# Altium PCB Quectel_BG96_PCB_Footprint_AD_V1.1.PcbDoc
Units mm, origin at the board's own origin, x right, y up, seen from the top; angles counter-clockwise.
Board outline 152.4 x 101.6 mm, 4 copper layers (Top, Inner Layer 2, Inner Layer 3, Bottom), stack 0.899 mm thick; 1 components, 0 nets, 102 pads, 0 vias.
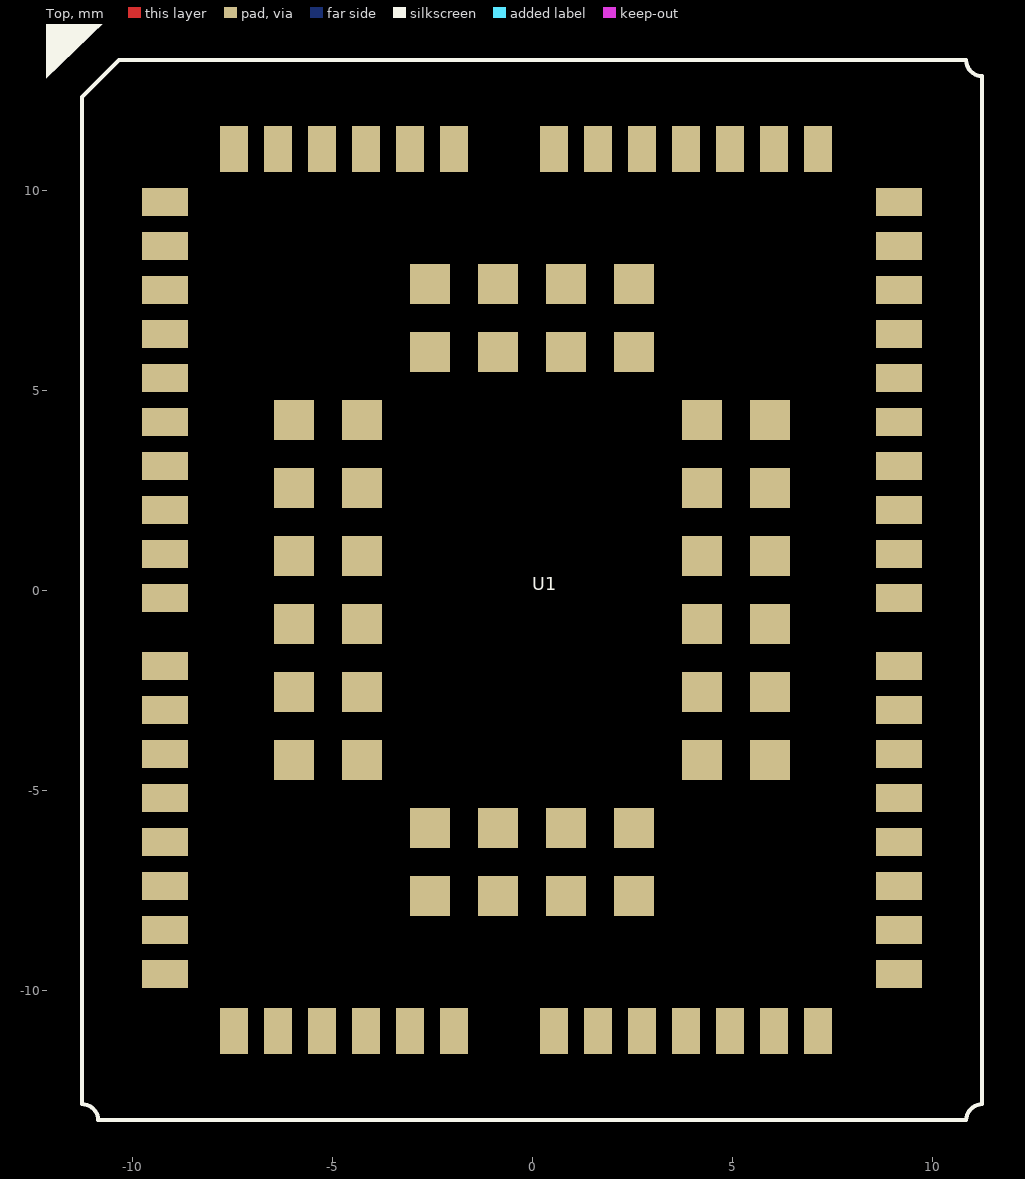
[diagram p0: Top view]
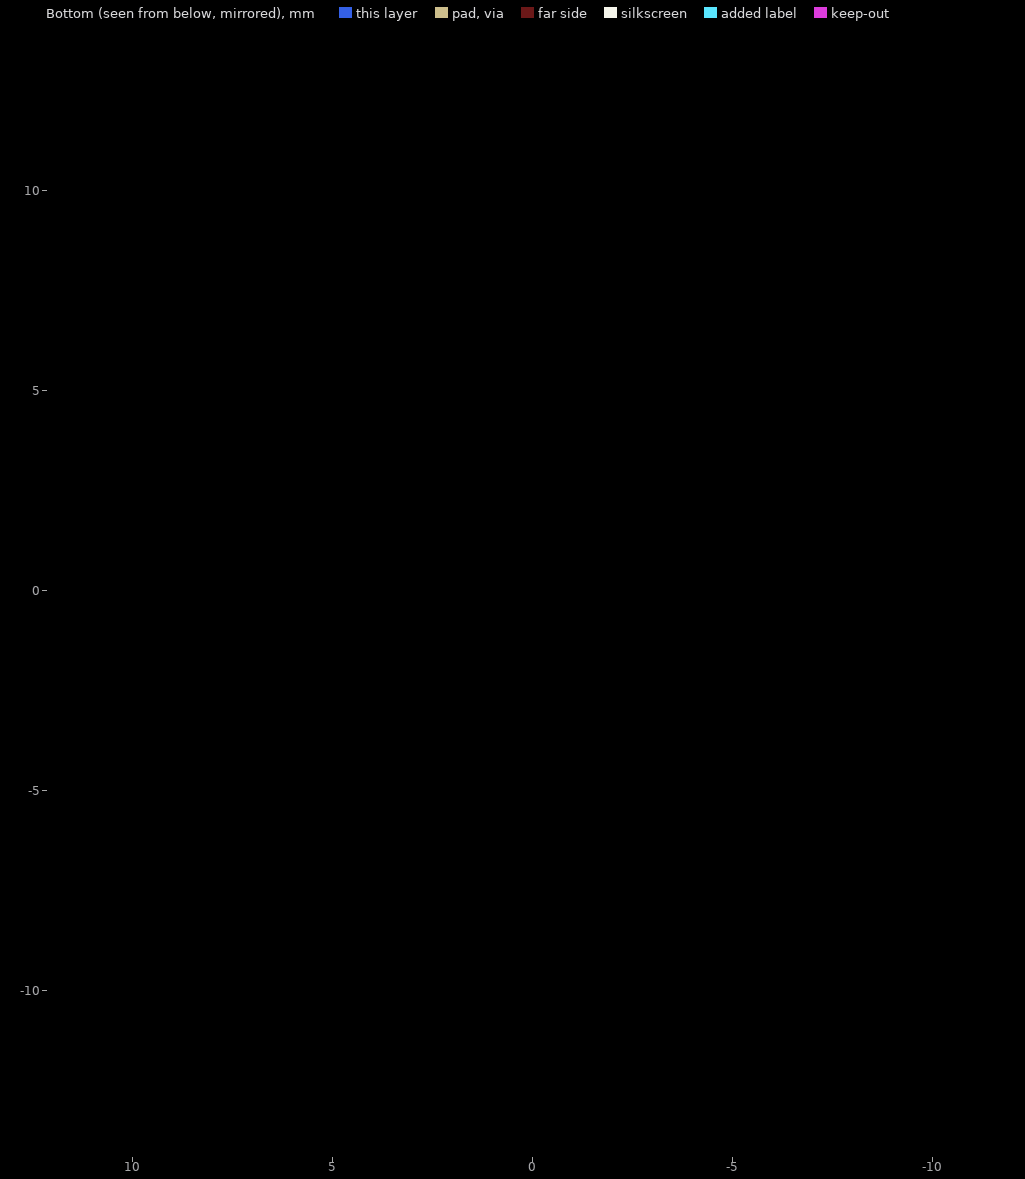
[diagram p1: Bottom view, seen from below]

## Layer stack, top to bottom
Top: signal copper 0.0343
Dielectric: dielectric 0.254, FR-4, Dk 4.3
Inner Layer 2: signal copper 0.0343
Dielectric: dielectric 0.254, FR-4, Dk 4.3
Inner Layer 3: signal copper 0.0343
Dielectric: dielectric 0.254, FR-4, Dk 4.3
Bottom: signal copper 0.0343

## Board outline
-228.6,-228.6 -76.2,-228.6 -76.2,-127 -228.6,-127

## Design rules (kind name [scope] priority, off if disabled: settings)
Clearance "'Default' PADS rule_18" [All] p1: gap=0.152
Clearance "'Default' PADS rule_15" [IsVia vs IsVia] p2: gap=0.152
ComponentClearance "'Default' PADS rule_12" [All] p1: gap=0.152 collisioncheckmode=3 verticalgap=0.254 showdistances=FALSE
FlightTimeFalling "'Default' PADS rule_10" [All] p1: maximum=10.00
FlightTimeRising "'Default' PADS rule_9" [All] p1: maximum=10.00
Length "'Default' PADS rule_5" [All] p1: maxlimit=1270 minlimit=0
MatchedLengths "'Default' PADS rule_11" [InNetClass('All Nets')] p1: tolerance=5.08 checknetsindiffpair=TRUE checkdiffpairvsdiffpair=TRUE checkothers=TRUE
MaxMinImpedance "'Default' PADS rule_8" [All] p1: minimum=50.00 maximum=150.0
ParallelSegment "'Default' PADS rule_7" [All] p1: limit=25.4 gap=5.08
ParallelSegment "'Default' PADS rule_6" [All] p2: limit=25.4 gap=5.08
PlaneClearance "'Default' PADS rule_14" [All] p1: clearance=0.152
PlaneConnect "Power Plane Connect Style - Via from round thru-hole global defaults" [IsVia] p1: planeconnectstyle=Relief reliefexpansion=0.508 reliefentries=4 reliefconductorwidth=0.381 reliefairgap=0.254
PlaneConnect "Power Plane Connect Style - Round thru-hole pad from global defaults" [IsPad And OnMultiLayer And (PadShape_MidLayer1 = 'Round') And (PadXSize_MidLayer1 = PadYSize_MidLayer1)] p2: planeconnectstyle=Relief reliefexpansion=0.508 reliefentries=4 reliefconductorwidth=0.381 reliefairgap=0.254
PlaneConnect "Power Plane Connect Style - Square thru-hole pad from global defaults" [IsPad And OnMultiLayer And ((PadShape_MidLayer1 = 'Rectangular') Or (PadShape_MidLayer1 = 'Octagonal') Or (PadShape_MidLayer1 = 'Rounded Rectangle')) And (PadXSize_MidLayer1 = PadYSize_MidLayer1)] p3: planeconnectstyle=Relief reliefexpansion=0.508 reliefentries=4 reliefconductorwidth=0.381 reliefairgap=0.254
PlaneConnect "Power Plane Connect Style - Rect thru-hole pad from global defaults" [IsPad And OnMultiLayer And ((PadShape_MidLayer1 = 'Rectangular') Or (PadShape_MidLayer1 = 'Octagonal') Or (PadShape_MidLayer1 = 'Rounded Rectangle')) And (PadXSize_MidLayer1 <> PadYSize_MidLayer1)] p4: planeconnectstyle=Relief reliefexpansion=0.508 reliefentries=4 reliefconductorwidth=0.381 reliefairgap=0.254
PlaneConnect "Power Plane Connect Style - Square-rect thru-hole pad from global defaults" [IsPad And OnMultiLayer And (PadShape_MidLayer1 = 'Rounded Rectangle') And (PadXSize_MidLayer1 = PadYSize_MidLayer1) And (Pad_CornerRadius_MidLayer1 = '0%')] p5: planeconnectstyle=Relief reliefexpansion=0.508 reliefentries=4 reliefconductorwidth=0.381 reliefairgap=0.254
PlaneConnect "Power Plane Connect Style - Oval thru-hole pad from global defaults" [IsPad And OnMultiLayer And (PadShape_MidLayer1 = 'Round') And (PadXSize_MidLayer1 <> PadYSize_MidLayer1)] p6: planeconnectstyle=Relief reliefexpansion=0.508 reliefentries=4 reliefconductorwidth=0.381 reliefairgap=0.254
PlaneConnect "Power Plane Connect Style - Round-oval thru-hole pad from global defaults" [IsPad And OnMultiLayer And (PadShape_MidLayer1 = 'Rounded Rectangle') And (PadXSize_MidLayer1 = PadYSize_MidLayer1) And (Pad_CornerRadius_MidLayer1 = '100%')] p7: planeconnectstyle=Relief reliefexpansion=0.508 reliefentries=4 reliefconductorwidth=0.381 reliefairgap=0.254
PolygonConnect "Polygon Connect Style - Bottom Round SMD from global defaults" [IsSMTPin And (PadShape_BottomLayer = 'Round') And (PadXSize_BottomLayer = PADYSize_BottomLayer) vs Layer = 'Bottom'] p1: connectstyle=Relief reliefconductorwidth=0.254 reliefentries=4 polygonreliefangle="45 Angle" airgapwidth=0.254
PolygonConnect "Polygon Connect Style - Top Round SMD from global defaults" [IsSMTPin And (PadShape_TopLayer = 'Round') And (PadXSize_TopLayer = PADYSize_TopLayer) vs Layer = 'Top'] p2: connectstyle=Relief reliefconductorwidth=0.254 reliefentries=4 polygonreliefangle="45 Angle" airgapwidth=0.254
PolygonConnect "Polygon Connect Style - Bottom Square SMD from global defaults 1" [IsSMTPin And (PadShape_BottomLayer = 'Rectangular') And (PadXSize_BottomLayer = PADYSize_BottomLayer) vs Layer = 'Bottom'] p3: connectstyle=Relief reliefconductorwidth=0.254 reliefentries=4 polygonreliefangle="45 Angle" airgapwidth=0.254
PolygonConnect "Polygon Connect Style - Bottom Square SMD from global defaults 2" [IsSMTPin And (PadShape_BottomLayer = 'Octagonal') And (PadXSize_BottomLayer = PADYSize_BottomLayer) vs Layer = 'Bottom'] p4: connectstyle=Relief reliefconductorwidth=0.254 reliefentries=4 polygonreliefangle="45 Angle" airgapwidth=0.254
PolygonConnect "Polygon Connect Style - Bottom Square SMD from global defaults 3" [IsSMTPin And (PadShape_BottomLayer = 'Rounded Rectangle') And (PadXSize_BottomLayer = PADYSize_BottomLayer) vs Layer = 'Bottom'] p5: connectstyle=Relief reliefconductorwidth=0.254 reliefentries=4 polygonreliefangle="45 Angle" airgapwidth=0.254
PolygonConnect "Polygon Connect Style - Top Square SMD from global defaults 1" [IsSMTPin And (PadShape_TopLayer = 'Rectangular') And (PadXSize_TopLayer = PADYSize_TopLayer) vs Layer = 'Top'] p6: connectstyle=Relief reliefconductorwidth=0.254 reliefentries=4 polygonreliefangle="45 Angle" airgapwidth=0.254
PolygonConnect "Polygon Connect Style - Top Square SMD from global defaults 2" [IsSMTPin And (PadShape_TopLayer = 'Octagonal') And (PadXSize_TopLayer = PADYSize_TopLayer) vs Layer = 'Top'] p7: connectstyle=Relief reliefconductorwidth=0.254 reliefentries=4 polygonreliefangle="45 Angle" airgapwidth=0.254
PolygonConnect "Polygon Connect Style - Top Square SMD from global defaults 3" [IsSMTPin And (PadShape_TopLayer = 'Rounded Rectangle') And (PadXSize_TopLayer = PADYSize_TopLayer) vs Layer = 'Top'] p8: connectstyle=Relief reliefconductorwidth=0.254 reliefentries=4 polygonreliefangle="45 Angle" airgapwidth=0.254
PolygonConnect "Polygon Connect Style - Bottom Rect SMD from global defaults 1" [IsSMTPin And (PadShape_BottomLayer = 'Rectangular') And (PadXSize_BottomLayer <> PADYSize_BottomLayer) vs Layer = 'Bottom'] p9: connectstyle=Relief reliefconductorwidth=0.254 reliefentries=4 polygonreliefangle="45 Angle" airgapwidth=0.254
PolygonConnect "Polygon Connect Style - Bottom Rect SMD from global defaults 2" [IsSMTPin And (PadShape_BottomLayer = 'Octagonal') And (PadXSize_BottomLayer <> PADYSize_BottomLayer) vs Layer = 'Bottom'] p10: connectstyle=Relief reliefconductorwidth=0.254 reliefentries=4 polygonreliefangle="45 Angle" airgapwidth=0.254
PolygonConnect "Polygon Connect Style - Bottom Rect SMD from global defaults 3" [IsSMTPin And (PadShape_BottomLayer = 'Rounded Rectangle') And (PadXSize_BottomLayer <> PADYSize_BottomLayer) vs Layer = 'Bottom'] p11: connectstyle=Relief reliefconductorwidth=0.254 reliefentries=4 polygonreliefangle="45 Angle" airgapwidth=0.254
PolygonConnect "Polygon Connect Style - Bottom Square-rect SMD pad from global defaults" [IsSMTPin And (PadShape_BottomLayer = 'Rounded Rectangle') And (PadXSize_BottomLayer = PADYSize_BottomLayer) And (Pad_CornerRadius_BottomLayer = '0%') vs Layer = 'Bottom'] p12: connectstyle=Relief reliefconductorwidth=0.254 reliefentries=4 polygonreliefangle="45 Angle" airgapwidth=0.254
PolygonConnect "Polygon Connect Style - Top Rect SMD from global defaults 1" [IsSMTPin And (PadShape_TopLayer = 'Rectangular') And (PadXSize_TopLayer <> PADYSize_TopLayer) vs Layer = 'Top'] p13: connectstyle=Relief reliefconductorwidth=0.254 reliefentries=4 polygonreliefangle="45 Angle" airgapwidth=0.254
PolygonConnect "Polygon Connect Style - Top Rect SMD from global defaults 2" [IsSMTPin And (PadShape_TopLayer = 'Octagonal') And (PadXSize_TopLayer <> PADYSize_TopLayer) vs Layer = 'Top'] p14: connectstyle=Relief reliefconductorwidth=0.254 reliefentries=4 polygonreliefangle="45 Angle" airgapwidth=0.254
PolygonConnect "Polygon Connect Style - Top Rect SMD from global defaults 3" [IsSMTPin And (PadShape_TopLayer = 'Rounded Rectangle') And (PadXSize_TopLayer <> PADYSize_TopLayer) vs Layer = 'Top'] p15: connectstyle=Relief reliefconductorwidth=0.254 reliefentries=4 polygonreliefangle="45 Angle" airgapwidth=0.254
PolygonConnect "Polygon Connect Style - Top Square-rect SMD pad from global defaults" [IsSMTPin And (PadShape_TopLayer = 'Rounded Rectangle') And (PadXSize_TopLayer = PADYSize_TopLayer) And (Pad_CornerRadius_TopLayer = '0%') vs Layer = 'Top'] p16: connectstyle=Relief reliefconductorwidth=0.254 reliefentries=4 polygonreliefangle="45 Angle" airgapwidth=0.254
PolygonConnect "Polygon Connect Style - Bottom Oval SMD from global defaults" [IsSMTPin And (PadShape_BottomLayer = 'Round') And (PadXSize_BottomLayer <> PADYSize_BottomLayer) vs Layer = 'Bottom'] p17: connectstyle=Relief reliefconductorwidth=0.254 reliefentries=4 polygonreliefangle="45 Angle" airgapwidth=0.254
PolygonConnect "Polygon Connect Style - Bottom Round-oval SMD pad from global defaults" [IsSMTPin And (PadShape_BottomLayer = 'Rounded Rectangle') And (PadXSize_BottomLayer = PADYSize_BottomLayer) And (Pad_CornerRadius_BottomLayer = '100%') vs Layer = 'Bottom'] p18: connectstyle=Relief reliefconductorwidth=0.254 reliefentries=4 polygonreliefangle="45 Angle" airgapwidth=0.254
PolygonConnect "Polygon Connect Style - Top Oval SMD from global defaults" [IsSMTPin And (PadShape_TopLayer = 'Round') And (PadXSize_TopLayer <> PADYSize_TopLayer) vs Layer = 'Top'] p19: connectstyle=Relief reliefconductorwidth=0.254 reliefentries=4 polygonreliefangle="45 Angle" airgapwidth=0.254
PolygonConnect "Polygon Connect Style - Top Round-oval SMD pad from global defaults" [IsSMTPin And (PadShape_TopLayer = 'Rounded Rectangle') And (PadXSize_TopLayer = PADYSize_TopLayer) And (Pad_CornerRadius_TopLayer = '100%') vs Layer = 'Top'] p20: connectstyle=Relief reliefconductorwidth=0.254 reliefentries=4 polygonreliefangle="45 Angle" airgapwidth=0.254
PolygonConnect "Polygon Connect Style - Via from round thru-hole global defaults_21" [IsVia] p21: connectstyle=Relief reliefconductorwidth=0.381 reliefentries=4 polygonreliefangle="45 Angle" airgapwidth=0.254
PolygonConnect "Polygon Connect Style - Bottom Round thru-hole pad from global defaults" [IsPad And OnMultiLayer And (PadShape_BottomLayer = 'Round') And (PadXSize_BottomLayer = PADYSize_BottomLayer) vs Layer = 'Bottom'] p22: connectstyle=Relief reliefconductorwidth=0.381 reliefentries=4 polygonreliefangle="45 Angle" airgapwidth=0.254
PolygonConnect "Polygon Connect Style - Via from round thru-hole global defaults_20" [IsVia] p23: connectstyle=Relief reliefconductorwidth=0.381 reliefentries=4 polygonreliefangle="45 Angle" airgapwidth=0.254
PolygonConnect "Polygon Connect Style - Inner Layer 3 Round thru-hole pad from global defaults" [IsPad And OnMultiLayer And (PadShape_MidLayer2 = 'Round') And (PadXSize_MidLayer2 = PADYSize_MidLayer2) vs Layer = 'Inner Layer 3'] p24: connectstyle=Relief reliefconductorwidth=0.381 reliefentries=4 polygonreliefangle="45 Angle" airgapwidth=0.254
PolygonConnect "Polygon Connect Style - Via from round thru-hole global defaults_19" [IsVia] p25: connectstyle=Relief reliefconductorwidth=0.381 reliefentries=4 polygonreliefangle="45 Angle" airgapwidth=0.254
PolygonConnect "Polygon Connect Style - Inner Layer 2 Round thru-hole pad from global defaults" [IsPad And OnMultiLayer And (PadShape_MidLayer1 = 'Round') And (PadXSize_MidLayer1 = PADYSize_MidLayer1) vs Layer = 'Inner Layer 2'] p26: connectstyle=Relief reliefconductorwidth=0.381 reliefentries=4 polygonreliefangle="45 Angle" airgapwidth=0.254
PolygonConnect "Polygon Connect Style - Via from round thru-hole global defaults" [IsVia] p27: connectstyle=Relief reliefconductorwidth=0.381 reliefentries=4 polygonreliefangle="45 Angle" airgapwidth=0.254
PolygonConnect "Polygon Connect Style - Top Round thru-hole pad from global defaults" [IsPad And OnMultiLayer And (PadShape_TopLayer = 'Round') And (PadXSize_TopLayer = PADYSize_TopLayer) vs Layer = 'Top'] p28: connectstyle=Relief reliefconductorwidth=0.381 reliefentries=4 polygonreliefangle="45 Angle" airgapwidth=0.254
PolygonConnect "Polygon Connect Style - Bottom Square thru-hole pad from global defaults" [IsPad And OnMultiLayer And ((PadShape_BottomLayer = 'Rectangular') Or (PadShape_BottomLayer = 'Octagonal') Or (PadShape_BottomLayer = 'Rounded Rectangle')) And (PadXSize_BottomLayer = PADYSize_BottomLayer) vs Layer = 'Bottom'] p29: connectstyle=Relief reliefconductorwidth=0.381 reliefentries=4 polygonreliefangle="45 Angle" airgapwidth=0.254
PolygonConnect "Polygon Connect Style - Inner Layer 3 Square thru-hole pad from global defaults" [IsPad And OnMultiLayer And ((PadShape_MidLayer2 = 'Rectangular') Or (PadShape_MidLayer2 = 'Octagonal') Or (PadShape_MidLayer2 = 'Rounded Rectangle')) And (PadXSize_MidLayer2 = PADYSize_MidLayer2) vs Layer = 'Inner Layer 3'] p30: connectstyle=Relief reliefconductorwidth=0.381 reliefentries=4 polygonreliefangle="45 Angle" airgapwidth=0.254
PolygonConnect "Polygon Connect Style - Inner Layer 2 Square thru-hole pad from global defaults" [IsPad And OnMultiLayer And ((PadShape_MidLayer1 = 'Rectangular') Or (PadShape_MidLayer1 = 'Octagonal') Or (PadShape_MidLayer1 = 'Rounded Rectangle')) And (PadXSize_MidLayer1 = PADYSize_MidLayer1) vs Layer = 'Inner Layer 2'] p31: connectstyle=Relief reliefconductorwidth=0.381 reliefentries=4 polygonreliefangle="45 Angle" airgapwidth=0.254
PolygonConnect "Polygon Connect Style - Top Square thru-hole pad from global defaults" [IsPad And OnMultiLayer And ((PadShape_TopLayer = 'Rectangular') Or (PadShape_TopLayer = 'Octagonal') Or (PadShape_TopLayer = 'Rounded Rectangle')) And (PadXSize_TopLayer = PADYSize_TopLayer) vs Layer = 'Top'] p32: connectstyle=Relief reliefconductorwidth=0.381 reliefentries=4 polygonreliefangle="45 Angle" airgapwidth=0.254
PolygonConnect "Polygon Connect Style - Bottom Rect thru-hole pad from global defaults" [IsPad And OnMultiLayer And ((PadShape_BottomLayer = 'Rectangular') Or (PadShape_BottomLayer = 'Octagonal') Or (PadShape_BottomLayer = 'Rounded Rectangle')) And (PadXSize_BottomLayer <> PADYSize_BottomLayer) vs Layer = 'Bottom'] p33: connectstyle=Relief reliefconductorwidth=0.381 reliefentries=4 polygonreliefangle="45 Angle" airgapwidth=0.254
PolygonConnect "Polygon Connect Style - Bottom Square-rect thru-hole pad from global defaults" [IsPad And OnMultiLayer And (PadShape_BottomLayer = 'Rounded Rectangle') And (PadXSize_BottomLayer = PADYSize_BottomLayer) And (Pad_CornerRadius_BottomLayer = '0%') vs Layer = 'Bottom'] p34: connectstyle=Relief reliefconductorwidth=0.381 reliefentries=4 polygonreliefangle="45 Angle" airgapwidth=0.254
PolygonConnect "Polygon Connect Style - Inner Layer 3 Rect thru-hole pad from global defaults" [IsPad And OnMultiLayer And ((PadShape_MidLayer2 = 'Rectangular') Or (PadShape_MidLayer2 = 'Octagonal') Or (PadShape_MidLayer2 = 'Rounded Rectangle')) And (PadXSize_MidLayer2 <> PADYSize_MidLayer2) vs Layer = 'Inner Layer 3'] p35: connectstyle=Relief reliefconductorwidth=0.381 reliefentries=4 polygonreliefangle="45 Angle" airgapwidth=0.254
PolygonConnect "Polygon Connect Style - Inner Layer 3 Square-rect thru-hole pad from global defaults" [IsPad And OnMultiLayer And (PadShape_MidLayer2 = 'Rounded Rectangle') And (PadXSize_MidLayer2 = PADYSize_MidLayer2) And (Pad_CornerRadius_MidLayer2 = '0%') vs Layer = 'Inner Layer 3'] p36: connectstyle=Relief reliefconductorwidth=0.381 reliefentries=4 polygonreliefangle="45 Angle" airgapwidth=0.254
PolygonConnect "Polygon Connect Style - Inner Layer 2 Rect thru-hole pad from global defaults" [IsPad And OnMultiLayer And ((PadShape_MidLayer1 = 'Rectangular') Or (PadShape_MidLayer1 = 'Octagonal') Or (PadShape_MidLayer1 = 'Rounded Rectangle')) And (PadXSize_MidLayer1 <> PADYSize_MidLayer1) vs Layer = 'Inner Layer 2'] p37: connectstyle=Relief reliefconductorwidth=0.381 reliefentries=4 polygonreliefangle="45 Angle" airgapwidth=0.254
PolygonConnect "Polygon Connect Style - Inner Layer 2 Square-rect thru-hole pad from global defaults" [IsPad And OnMultiLayer And (PadShape_MidLayer1 = 'Rounded Rectangle') And (PadXSize_MidLayer1 = PADYSize_MidLayer1) And (Pad_CornerRadius_MidLayer1 = '0%') vs Layer = 'Inner Layer 2'] p38: connectstyle=Relief reliefconductorwidth=0.381 reliefentries=4 polygonreliefangle="45 Angle" airgapwidth=0.254
PolygonConnect "Polygon Connect Style - Top Rect thru-hole pad from global defaults" [IsPad And OnMultiLayer And ((PadShape_TopLayer = 'Rectangular') Or (PadShape_TopLayer = 'Octagonal') Or (PadShape_TopLayer = 'Rounded Rectangle')) And (PadXSize_TopLayer <> PADYSize_TopLayer) vs Layer = 'Top'] p39: connectstyle=Relief reliefconductorwidth=0.381 reliefentries=4 polygonreliefangle="45 Angle" airgapwidth=0.254
PolygonConnect "Polygon Connect Style - Top Square-rect thru-hole pad from global defaults" [IsPad And OnMultiLayer And (PadShape_TopLayer = 'Rounded Rectangle') And (PadXSize_TopLayer = PADYSize_TopLayer) And (Pad_CornerRadius_TopLayer = '0%') vs Layer = 'Top'] p40: connectstyle=Relief reliefconductorwidth=0.381 reliefentries=4 polygonreliefangle="45 Angle" airgapwidth=0.254
PolygonConnect "Polygon Connect Style - Bottom Oval thru-hole pad from global defaults" [IsPad And OnMultiLayer And (PadShape_BottomLayer = 'Round') And (PadXSize_BottomLayer <> PADYSize_BottomLayer) vs Layer = 'Bottom'] p41: connectstyle=Relief reliefconductorwidth=0.381 reliefentries=4 polygonreliefangle="45 Angle" airgapwidth=0.254
PolygonConnect "Polygon Connect Style - Bottom Round-oval thru-hole pad from global defaults" [IsPad And OnMultiLayer And (PadShape_BottomLayer = 'Rounded Rectangle') And (PadXSize_BottomLayer = PADYSize_BottomLayer) And (Pad_CornerRadius_BottomLayer = '100%') vs Layer = 'Bottom'] p42: connectstyle=Relief reliefconductorwidth=0.381 reliefentries=4 polygonreliefangle="45 Angle" airgapwidth=0.254
PolygonConnect "Polygon Connect Style - Inner Layer 3 Oval thru-hole pad from global defaults" [IsPad And OnMultiLayer And (PadShape_MidLayer2 = 'Round') And (PadXSize_MidLayer2 <> PADYSize_MidLayer2) vs Layer = 'Inner Layer 3'] p43: connectstyle=Relief reliefconductorwidth=0.381 reliefentries=4 polygonreliefangle="45 Angle" airgapwidth=0.254
PolygonConnect "Polygon Connect Style - Inner Layer 3 Round-oval thru-hole pad from global defaults" [IsPad And OnMultiLayer And (PadShape_MidLayer2 = 'Rounded Rectangle') And (PadXSize_MidLayer2 = PADYSize_MidLayer2) And (Pad_CornerRadius_MidLayer2 = '100%') vs Layer = 'Inner Layer 3'] p44: connectstyle=Relief reliefconductorwidth=0.381 reliefentries=4 polygonreliefangle="45 Angle" airgapwidth=0.254
PolygonConnect "Polygon Connect Style - Inner Layer 2 Oval thru-hole pad from global defaults" [IsPad And OnMultiLayer And (PadShape_MidLayer1 = 'Round') And (PadXSize_MidLayer1 <> PADYSize_MidLayer1) vs Layer = 'Inner Layer 2'] p45: connectstyle=Relief reliefconductorwidth=0.381 reliefentries=4 polygonreliefangle="45 Angle" airgapwidth=0.254
PolygonConnect "Polygon Connect Style - Inner Layer 2 Round-oval thru-hole pad from global defaults" [IsPad And OnMultiLayer And (PadShape_MidLayer1 = 'Rounded Rectangle') And (PadXSize_MidLayer1 = PADYSize_MidLayer1) And (Pad_CornerRadius_MidLayer1 = '100%') vs Layer = 'Inner Layer 2'] p46: connectstyle=Relief reliefconductorwidth=0.381 reliefentries=4 polygonreliefangle="45 Angle" airgapwidth=0.254
PolygonConnect "Polygon Connect Style - Top Oval thru-hole pad from global defaults" [IsPad And OnMultiLayer And (PadShape_TopLayer = 'Round') And (PadXSize_TopLayer <> PADYSize_TopLayer) vs Layer = 'Top'] p47: connectstyle=Relief reliefconductorwidth=0.381 reliefentries=4 polygonreliefangle="45 Angle" airgapwidth=0.254
PolygonConnect "Polygon Connect Style - Top Round-oval thru-hole pad from global defaults" [IsPad And OnMultiLayer And (PadShape_TopLayer = 'Rounded Rectangle') And (PadXSize_TopLayer = PADYSize_TopLayer) And (Pad_CornerRadius_TopLayer = '100%') vs Layer = 'Top'] p48: connectstyle=Relief reliefconductorwidth=0.381 reliefentries=4 polygonreliefangle="45 Angle" airgapwidth=0.254
PolygonConnect [All] p49: connectstyle=Relief reliefconductorwidth=0.254 reliefentries=4 polygonreliefangle="90 Angle" airgapwidth=0.254
RoutingLayers "'Default' PADS rule_3" [All] p1: top layer_v5=TRUE mid layer 1_v5=TRUE mid layer 2_v5=TRUE bottom layer_v5=TRUE
RoutingPriority "'Default' PADS rule_2" [All] p1: routingpriority=3
RoutingTopology "'Default' PADS rule" [All] p1: topology=Shortest
RoutingVias "'Default' PADS rule_4" [All] p1: holewidth=0.94 width=1.397 viastyle="Through Hole" minholewidth=0.94 minwidth=1.397 maxholewidth=0.94 maxwidth=1.397
SMDToCorner "'Default' PADS rule_16" [All] p1: distance=60000
SMDToPlane "'Default' PADS rule_17" [All] p1: distance=60000
SolderMaskExpansion [All] p1: expansion=0.102
Width "'Default' PADS rule_13" [All] p1: maxlimit=0.305 minlimit=0.305 preferedwidth=0.305
22 further rules are at their usual default settings.

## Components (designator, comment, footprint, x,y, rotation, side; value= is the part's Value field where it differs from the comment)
U1 "BG96" BG96 0,0 r0 top

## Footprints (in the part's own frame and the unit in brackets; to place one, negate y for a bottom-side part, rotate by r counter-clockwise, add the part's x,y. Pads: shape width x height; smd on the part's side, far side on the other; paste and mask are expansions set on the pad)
BG96 [mm]
  rect 1.15x0.7 smd mask+0.05: 1(-9.175,9.7) 2(-9.175,8.6) 3(-9.175,7.5) 4(-9.175,6.4) 5(-9.175,5.3) 6(-9.175,4.2) 7(-9.175,3.1) 8(-9.175,2) 9(-9.175,0.9) 10(-9.175,-0.2) 11(-9.175,-1.9) 12(-9.175,-3) 13(-9.175,-4.1) 14(-9.175,-5.2) 15(-9.175,-6.3) 16(-9.175,-7.4) 17(-9.175,-8.5) 18(-9.175,-9.6) 32(9.175,-9.6) 33(9.175,-8.5) 34(9.175,-7.4) 35(9.175,-6.3) 36(9.175,-5.2) 37(9.175,-4.1) 38(9.175,-3) 39(9.175,-1.9) 40(9.175,-0.2) 41(9.175,0.9) 42(9.175,2) 43(9.175,3.1) 44(9.175,4.2) 45(9.175,5.3) 46(9.175,6.4) 47(9.175,7.5) 48(9.175,8.6) 49(9.175,9.7)
  rect 0.7x1.15 smd mask+0.05: 19(-7.45,-11.025) 20(-6.35,-11.025) 21(-5.25,-11.025) 22(-4.15,-11.025) 23(-3.05,-11.025) 24(-1.95,-11.025) 25(0.55,-11.025) 26(1.65,-11.025) 27(2.75,-11.025) 28(3.85,-11.025) 29(4.95,-11.025) 30(6.05,-11.025) 31(7.15,-11.025) 50(7.15,11.025) 51(6.05,11.025) 52(4.95,11.025) 53(3.85,11.025) 54(2.75,11.025) 55(1.65,11.025) 56(0.55,11.025) 57(-1.95,11.025) 58(-3.05,11.025) 59(-4.15,11.025) 60(-5.25,11.025) 61(-6.35,11.025) 62(-7.45,11.025)
  rect 1x1 smd mask+0.05: 63(-5.95,4.25) 64(-5.95,2.55) 65(-5.95,0.85) 66(-5.95,-0.85) 67(-5.95,-2.55) 68(-5.95,-4.25) 69(-2.55,-7.65) 70(-0.85,-7.65) 71(0.85,-7.65) 72(2.55,-7.65) 73(5.95,-4.25) 74(5.95,-2.55) 75(5.95,-0.85) 76(5.95,0.85) 77(5.95,2.55) 78(5.95,4.25) 79(2.55,7.65) 80(0.85,7.65) 81(-0.85,7.65) 82(-2.55,7.65) 83(-4.25,4.25) 84(-4.25,2.55) 85(-4.25,0.85) 86(-4.25,-0.85) 87(-4.25,-2.55) 88(-4.25,-4.25) 89(-2.55,-5.95) 90(-0.85,-5.95) 91(0.85,-5.95) 92(2.55,-5.95) 93(4.25,-4.25) 94(4.25,-2.55) 95(4.25,-0.85) 96(4.25,0.85) 97(4.25,2.55) 98(4.25,4.25) 99(2.55,5.95) 100(0.85,5.95) 101(-0.85,5.95) 102(-2.55,5.95)
  silkscreen extent -12.18,-13.25 11.25,14.24

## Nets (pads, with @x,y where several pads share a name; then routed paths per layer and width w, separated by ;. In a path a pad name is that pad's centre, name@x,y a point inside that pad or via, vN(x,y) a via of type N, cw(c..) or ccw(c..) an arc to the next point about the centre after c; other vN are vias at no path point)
pads on no net: U1.1 U1.2 U1.3 U1.4 U1.5 U1.6 U1.7 U1.8 U1.9 U1.10 U1.11 U1.12 U1.13 U1.14 U1.15 U1.16 U1.17 U1.18 U1.19 U1.20 U1.21 U1.22 U1.23 U1.24 U1.25 U1.26 U1.27 U1.28 U1.29 U1.30 U1.31 U1.32 U1.33 U1.34 U1.35 U1.36 U1.37 U1.38 U1.39 U1.40 U1.41 U1.42 U1.43 U1.44 U1.45 U1.46 U1.47 U1.48 U1.49 U1.50 U1.51 U1.52 U1.53 U1.54 U1.55 U1.56 U1.57 U1.58 U1.59 U1.60 U1.61 U1.62 U1.63 U1.64 U1.65 U1.66 U1.67 U1.68 U1.69 U1.70 U1.71 U1.72 U1.73 U1.74 U1.75 U1.76 U1.77 U1.78 U1.79 U1.80 U1.81 U1.82 U1.83 U1.84 U1.85 U1.86 U1.87 U1.88 U1.89 U1.90 U1.91 U1.92 U1.93 U1.94 U1.95 U1.96 U1.97 U1.98 U1.99 U1.100 U1.101 U1.102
